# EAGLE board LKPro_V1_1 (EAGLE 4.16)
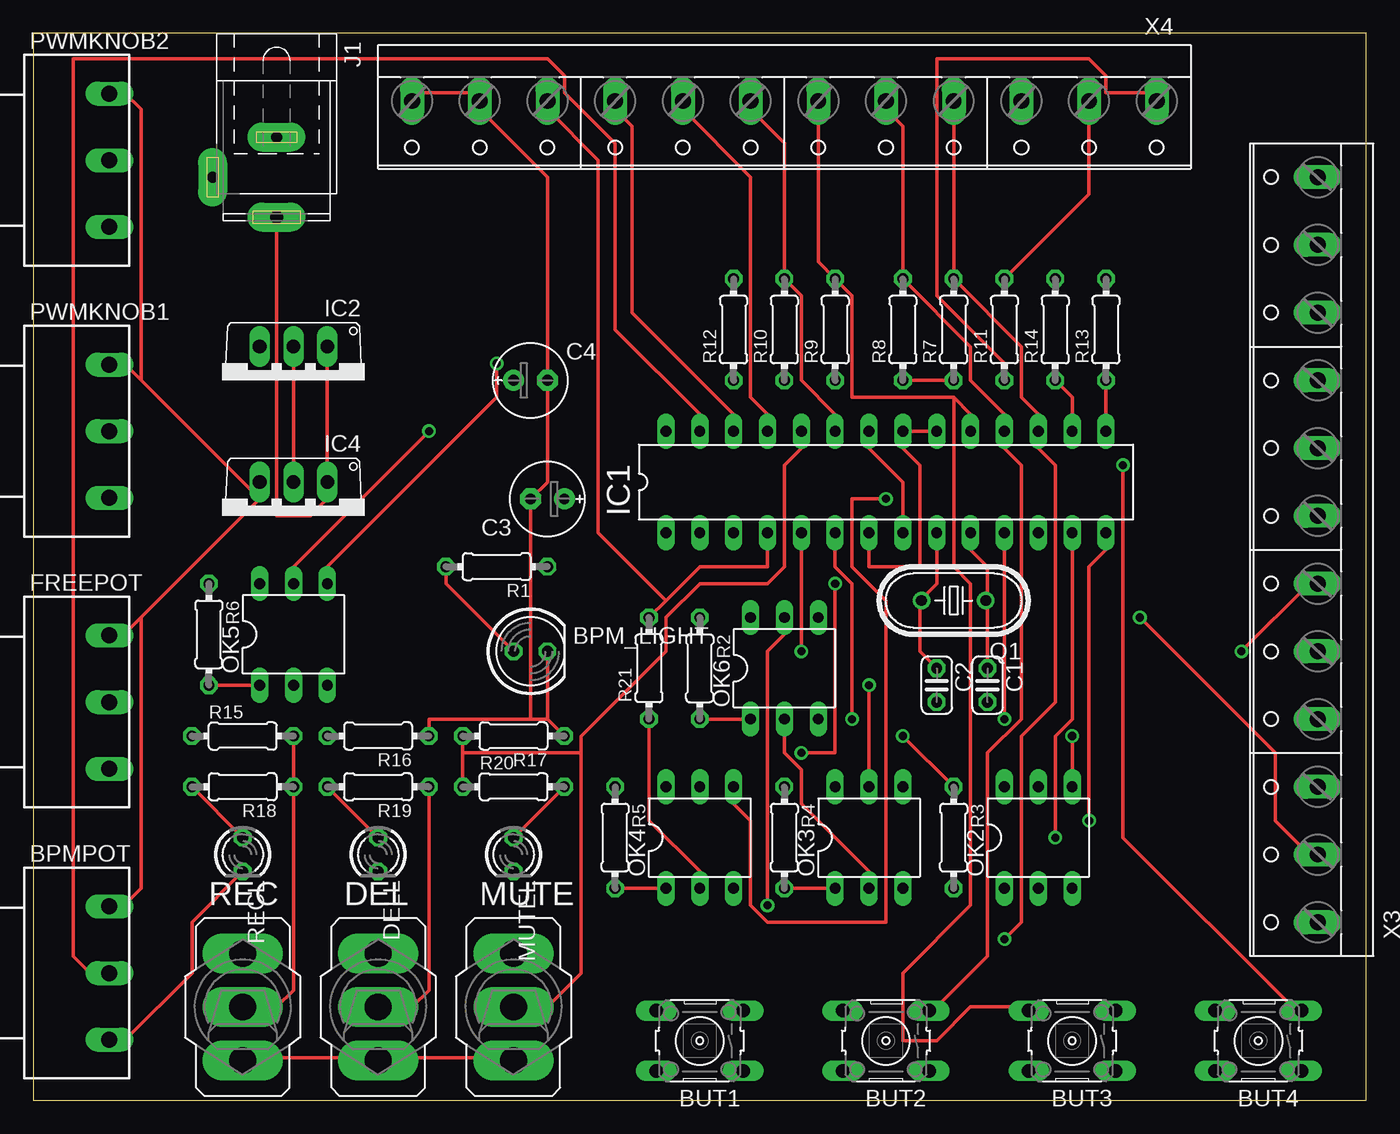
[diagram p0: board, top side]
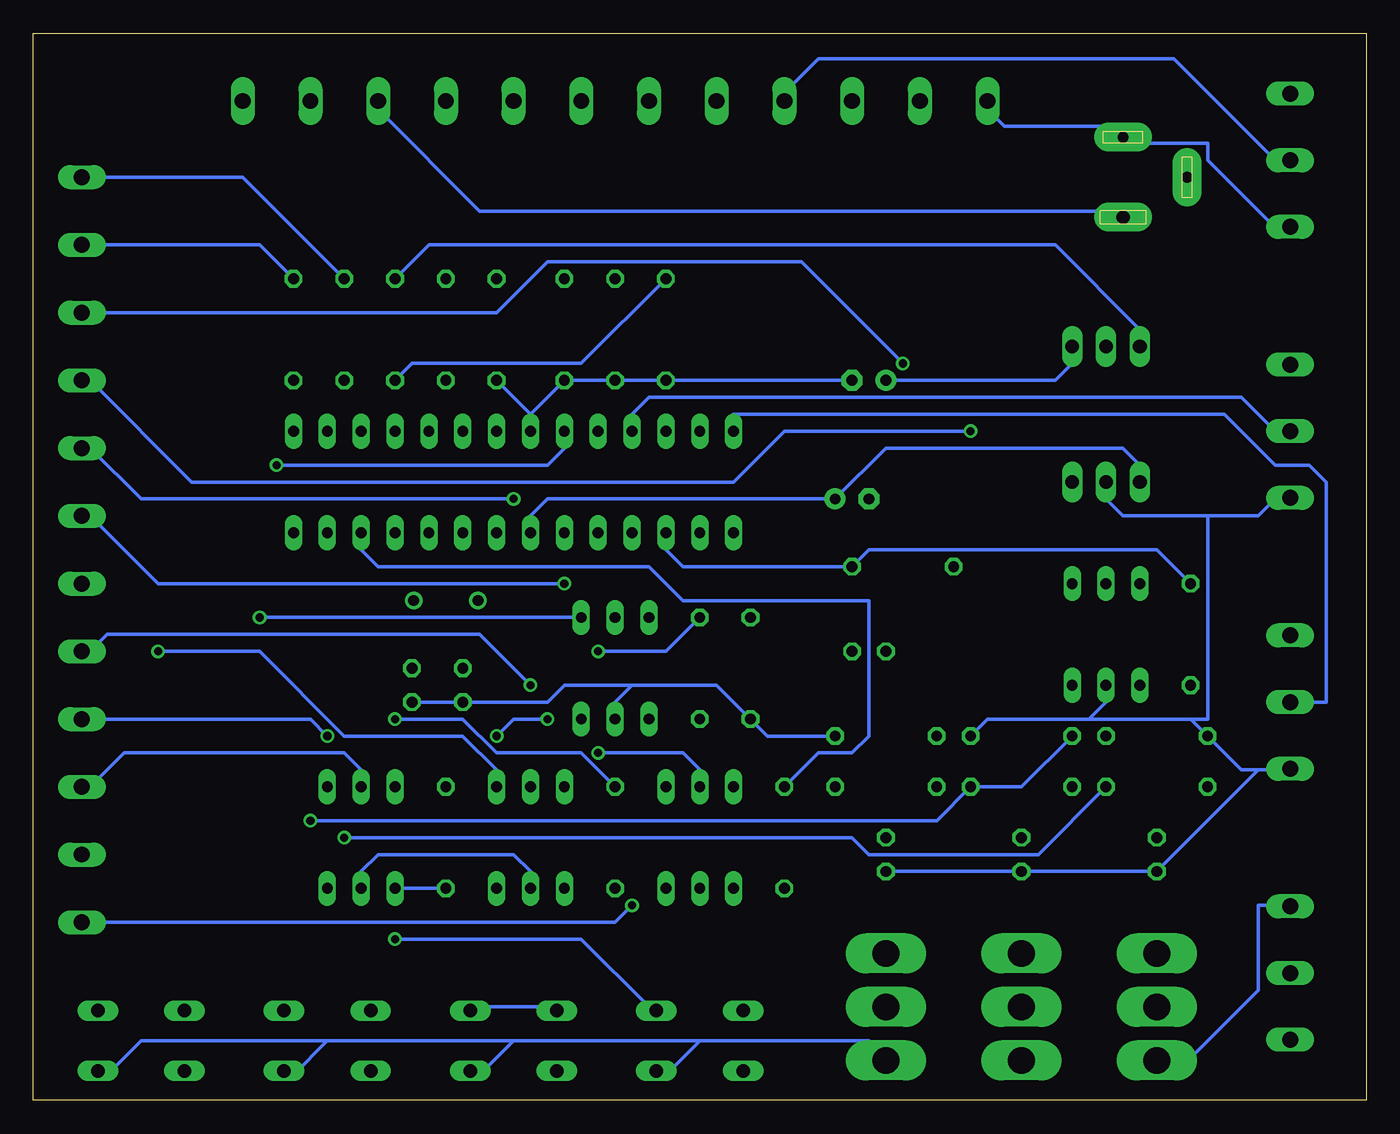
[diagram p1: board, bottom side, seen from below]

Size 100 x 80 mm. Coordinates in mm from the lower left corner, seen from the top.
Outline: 0,0 100,0 100,80 0,80 0,0
Copper layers (1*16): Top 0.035mm / dielectric 1.5mm / Bottom 0.035mm
Design rules "default": minimum track width 10mil, minimum drill 24mil, track to track 8mil, track to pad 8mil, pad to pad 8mil, via to via 8mil, smd to smd 8mil, copper to edge 40mil, drill to drill 8mil, minimum pad ring 10mil, minimum via ring 8mil, stop-mask expansion 4mil, vias tented up to drill 0mil, thermal gap 10mil

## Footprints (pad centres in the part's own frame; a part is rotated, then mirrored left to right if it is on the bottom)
LED5MM = drill 0.813 octagon: A -1.27,0; K 1.27,0
PC16S = drill 1.2 long: 1A -5,6.5; 1E 5,6.5; 1S 0,6.5
B3F-10XX = drill 1.016 long: 1 -3.251,2.261; 2 3.251,2.261; 3 -3.251,-2.261; 4 3.251,-2.261
C025-024X044 = drill 0.813 octagon: 1 -1.27,0; 2 1.27,0
E2,5-6E = drill 0.813 pad 1.575 round: + -1.27,0 | drill 0.813 pad 1.575 octagon: - 1.27,0
320-916 = drill 2.007 long: 1 0,4.013; 2 0,0; 3 0,-4.013
LED3MM = drill 0.813 octagon: A -1.27,0; K 1.27,0
DIL28-3 = drill 0.813 long: 1 -16.51,-3.81; 2 -13.97,-3.81; 3 -11.43,-3.81; 4 -8.89,-3.81; 5 -6.35,-3.81; 6 -3.81,-3.81; 7 -1.27,-3.81; 8 1.27,-3.81; 9 3.81,-3.81; 10 6.35,-3.81; 11 8.89,-3.81; 12 11.43,-3.81; 13 13.97,-3.81; 14 16.51,-3.81; 15 16.51,3.81; 16 13.97,3.81; 17 11.43,3.81; 18 8.89,3.81; 19 6.35,3.81; 20 3.81,3.81; 21 1.27,3.81; 22 -1.27,3.81; 23 -3.81,3.81; 24 -6.35,3.81; 25 -8.89,3.81; 26 -11.43,3.81; 27 -13.97,3.81; 28 -16.51,3.81
TO220V = drill 1.016 long: 1 -2.54,-2.54; 2 0,-2.54; 3 2.54,-2.54
SPC4077 = drill 0.8 pad 2.184 long: 1 -3,0; 2 0,-4.8 | drill 1 pad 2.184 long: 3 3,0
DIL06 = drill 0.813 long: 1 -2.54,-3.81; 2 0,-3.81; 3 2.54,-3.81; 4 2.54,3.81; 5 0,3.81; 6 -2.54,3.81
HC49U70 = drill 0.813 round: 1 -2.413,0; 2 2.413,0
0204/7 = drill 0.813 octagon: 1 -3.81,0; 2 3.81,0
W237-12P = drill 1.194 long: 1 -27.94,-0.635; 2 -22.86,-0.635; 3 -17.78,-0.635; 4 -12.7,-0.635; 5 -7.62,-0.635; 6 -2.54,-0.635; 7 2.54,-0.635; 8 7.62,-0.635; 9 12.7,-0.635; 10 17.78,-0.635; 11 22.86,-0.635; 12 27.94,-0.635

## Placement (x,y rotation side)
BPM_LIGHT  [LED5MM]  37.3,33.65 0 top
BPMPOT  PC16S  [PC16S]  -0.8,9.52 270 top
BUT1  [B3F-10XX]  50,4.44 180 top
BUT2  [B3F-10XX]  63.97,4.44 180 top
BUT3  [B3F-10XX]  77.94,4.44 180 top
BUT4  [B3F-10XX]  91.91,4.44 180 top
C1  22pF  [C025-024X044]  71.59,31.11 270 top
C2  22pF  [C025-024X044]  67.78,31.11 270 top
C3  1uF  [E2,5-6E]  38.57,45.08 180 top
C4  10uF  [E2,5-6E]  37.3,53.97 0 top
DEL  [320-916]  25.87,6.98 0 top
DELL  [LED3MM]  25.87,18.41 270 top
FREEPOT  PC16S  [PC16S]  -0.8,29.84 270 top
IC1  MEGA8-P  [DIL28-3]  63.97,46.35 0 top
IC2  7806  [TO220V]  19.52,53.97 180 top
IC4  7805  [TO220V]  19.52,43.81 180 top
J1  [SPC4077]  18.25,69.21 270 top
MUTE  [320-916]  36.03,6.98 0 top
MUTEL  [LED3MM]  36.03,18.41 270 top
OK2  4N35  [DIL06]  75.4,19.68 0 top
OK3  4N35  [DIL06]  62.7,19.68 0 top
OK4  4N35  [DIL06]  50,19.68 0 top
OK5  4N35  [DIL06]  19.52,34.92 0 top
OK6  4N35  [DIL06]  56.35,32.38 0 top
PWMKNOB1  PC16S  [PC16S]  -0.8,50.16 270 top
PWMKNOB2  PC16S  [PC16S]  -0.8,70.48 270 top
Q1  [HC49U70]  69.05,37.46 180 top
R1  220 Ohm  [0204/7]  34.76,40 180 top
R2  220 Ohm  [0204/7]  50,32.38 270 top
R3  220 Ohm  [0204/7]  69.05,19.68 270 top
R4  220 Ohm  [0204/7]  56.35,19.68 270 top
R5  220 Ohm  [0204/7]  43.65,19.68 270 top
R6  220 Ohm  [0204/7]  13.17,34.92 270 top
R7  1k Ohm  [0204/7]  69.05,57.78 90 top
R8  1k Ohm  [0204/7]  65.24,57.78 90 top
R9  1k Ohm  [0204/7]  60.16,57.78 90 top
R10  1k Ohm  [0204/7]  56.35,57.78 90 top
R11  1k Ohm  [0204/7]  72.86,57.78 90 top
R12  1k Ohm  [0204/7]  52.54,57.78 90 top
R13  220 Ohm  [0204/7]  80.48,57.78 90 top
R14  220 Ohm  [0204/7]  76.67,57.78 90 top
R15  1k Ohm  [0204/7]  15.71,27.3 0 top
R16  1k Ohm  [0204/7]  25.87,27.3 180 top
R17  1k Ohm  [0204/7]  36.03,27.3 180 top
R18  220 Ohm  [0204/7]  15.71,23.49 180 top
R19  220 Ohm  [0204/7]  25.87,23.49 180 top
R20  220 Ohm  [0204/7]  36.03,23.49 0 top
R21  1k Ohm  [0204/7]  46.19,32.38 90 top
REC  [320-916]  15.71,6.98 0 top
RECL  [LED3MM]  15.71,18.41 270 top
X3  [W237-12P]  95.72,41.27 90 top
X4  [W237-12P]  56.35,74.29 180 top

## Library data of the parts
BPM_LIGHT DELL MUTEL RECL = led
BPMPOT FREEPOT PWMKNOB1 PWMKNOB2 = piher
BUT1-BUT4 = switch-omron
C1-C4 R1-R21 = rcl
DEL MUTE REC = switch
IC1 = atmel
IC2 IC4 = linear
J1 = con-jack
OK2-OK6 = optocoupler
Q1 = crystal
X3 X4 = con-wago-508

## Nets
+12V: C4.+ IC2.1 IC4.1 J1.3 X4.3
GND: BPM_LIGHT.K BPMPOT.1E C1.2 C2.2 C3.- C4.- DELL.K FREEPOT.1E IC1.8 IC1.22 IC2.2 IC4.2 J1.1 MUTEL.K OK2.2 OK3.2 OK4.2 OK5.2 OK6.2 PWMKNOB1.1E PWMKNOB2.1E R7.1 R8.1 R9.1 R10.1 R12.1 R15.1 R16.1 R17.1 R21.1 RECL.K X4.11 X4.12
N$1: C2.1 IC1.9 Q1.2
N$2: C1.1 IC1.10 Q1.1
N$3: OK6.1 R2.2
N$4: BPMPOT.1A BUT1.1 BUT2.1 BUT3.1 BUT4.1 C3.+ DEL.3 FREEPOT.1A IC1.7 IC1.20 IC1.21 IC4.3 MUTE.3 PWMKNOB1.1A PWMKNOB2.1A REC.3
N$5: OK6.5 X3.1
N$6: IC1.3 R1.1 R6.1
N$7: BPM_LIGHT.A R1.2
N$8: OK2.1 R3.2
N$9: OK3.1 R4.2
N$10: OK4.1 R5.2
N$11: OK5.1 R6.2
N$12: OK6.4 X3.2
N$13: OK2.5 X3.3
N$14: OK2.4 X3.4
N$15: OK3.5 X3.5
N$16: OK3.4 X3.6
N$17: OK4.5 X3.7
N$18: OK4.4 X3.8
N$19: OK5.5 X3.9
N$20: OK5.4 X3.10
N$21: IC2.3 R11.2 X4.2
N$22: R11.1 R12.2 X4.1
N$23: DEL.2 IC1.14 R16.2 R19.1
N$24: IC1.5 R2.1
N$25: IC1.6 R3.1
N$26: IC1.11 R4.1
N$27: IC1.12 R5.1
N$28: BUT1.3 IC1.17 R7.2 X4.4
N$29: BUT2.3 BUT2.4 IC1.18 R8.2 X4.5
N$30: BUT3.4 IC1.19 R9.2 X4.6
N$31: BUT4.3 IC1.23 R10.2 X4.7
N$32: IC1.16 R14.1
N$33: IC1.15 R13.1
N$34: R13.2 X3.11
N$35: R14.2 X3.12
N$37: IC1.25 PWMKNOB1.1S X4.8
N$38: IC1.26 PWMKNOB2.1S X4.9
N$39: BPMPOT.1S IC1.27
N$40: R18.2 RECL.A
N$41: IC1.13 R15.2 R18.1 REC.2
N$42: IC1.24 MUTE.2 R17.2 R20.1
N$43: FREEPOT.1S IC1.28
N$44: MUTEL.A R20.2
N$45: DELL.A R19.2
N$47: IC1.4 R21.2 X4.10

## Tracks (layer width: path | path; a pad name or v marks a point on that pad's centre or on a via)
+12V
  Top 0.254: IC2.1 IC4.1 22.06,45.08 20.79,43.81 18.25,43.81 J1.3
  Bottom 0.254: C4.+ 23.33,53.97 22.06,55.24 IC2.1 | X4.3 74.13,74.29 66.51,66.67 19.52,66.67 J1.3
GND
  Top 0.254: X4.12 28.41,75.56 33.49,75.56 X4.11 33.49,74.29 38.57,69.21 C4.- 38.57,46.35 C3.- 37.3,28.57 | IC1.8 65.24,46.35 62.7,48.89 IC1.22 | R8.1 R7.1 | 38.57,28.57 R17.1 | 38.57,28.57 BPM_LIGHT.K | R21.1 46.19,20.95 50,17.14 OK4.2 | OK3.2 62.7,17.14 57.62,22.22 57.62,24.76 56.35,26.03 OK6.2 | RECL.K 11.9,13.33 11.9,9.52 6.82,4.44 BPMPOT.1E | IC4.2 IC2.2 | 37.3,28.57 29.68,28.57 R16.1 | 37.3,28.57 38.57,28.57
  Bottom 0.254: PWMKNOB2.1E 6.82,65.4 11.9,70.48 11.9,71.75 16.98,71.75 J1.1 19.52,73.02 27.14,73.02 28.41,74.29 X4.12 | 62.7,51.43 R9.1 R10.1 R12.1 C4.- | 62.7,51.43 R8.1 | 62.7,51.43 IC1.22 | C1.2 C2.2 61.43,29.84 60.16,31.11 55.08,31.11 | R17.1 44.92,27.3 R21.1 48.73,31.11 55.08,31.11 | 55.08,31.11 56.35,29.84 OK6.2 | OK2.2 75.4,17.14 74.13,18.41 63.97,18.41 62.7,17.14 OK3.2 | MUTEL.K DELL.K RECL.K 8.09,24.76 | 11.9,43.81 18.25,43.81 19.52,45.08 IC4.2 | 11.9,43.81 8.09,43.81 6.82,45.08 PWMKNOB1.1E | 8.09,24.76 6.82,24.76 FREEPOT.1E | 8.09,24.76 9.36,24.76 R15.1 13.17,28.57 | R16.1 28.41,28.57 20.79,28.57 | 20.79,28.57 19.52,29.84 OK5.2 | 13.17,28.57 20.79,28.57 | 11.9,43.81 11.9,28.57 13.17,28.57
N$1
  Top 0.254: 66.51,37.46 67.78,38.73 IC1.9 | C2.1 66.51,33.65 66.51,37.46 | 66.51,37.46 Q1.2
N$2
  Top 0.254: C1.1 71.59,37.46 | 71.59,37.46 71.59,40 70.32,41.27 IC1.10 | 71.59,37.46 Q1.1
N$3
  Top 0.254: R2.2 OK6.1
N$4
  Top 0.254: REC.3 18.25,3.17 23.33,3.17 DEL.3 28.41,3.17 33.49,3.17 MUTE.3 | IC1.20 IC1.21 65.24,48.89 66.51,47.62 66.51,40 62.7,40 IC1.7 | 8.09,36.19 6.82,34.92 FREEPOT.1A | 8.09,36.19 16.98,45.08 | 8.09,36.19 8.09,15.87 6.82,14.6 BPMPOT.1A | 16.98,45.08 8.09,53.97 | 8.09,53.97 6.82,55.24 PWMKNOB1.1A | 16.98,45.08 IC4.3 | 8.09,53.97 8.09,74.29 6.82,75.56 PWMKNOB2.1A
  Bottom 0.254: 50,4.44 52.54,1.9 BUT1.1 | 50,4.44 37.3,4.44 MUTE.3 | 63.97,4.44 66.51,1.9 BUT2.1 | 50,4.44 63.97,4.44 | 77.94,4.44 80.48,1.9 BUT3.1 | 63.97,4.44 77.94,4.44 | 77.94,4.44 91.91,4.44 94.45,1.9 BUT4.1 | IC1.7 62.7,43.81 61.43,45.08 C3.+ 36.03,48.89 18.25,48.89 16.98,47.62 IC4.3 | REC.3 13.17,3.17 8.09,8.25 8.09,14.6 6.82,14.6 BPMPOT.1A
N$5  (via drill 0.61)
  Top 0.254: v55.08,14.6 55.08,33.65 56.35,34.92 OK6.5
  Bottom 0.254: v55.08,14.6 56.35,13.33 X3.1
N$6
  Bottom 0.254: R6.1 15.71,41.27 37.3,41.27 R1.1 51.27,40 52.54,41.27 IC1.3
N$7
  Top 0.254: BPM_LIGHT.A 30.95,38.73 R1.2
N$8
  Bottom 0.254: R3.2 OK2.1
N$9
  Top 0.254: R4.2 OK3.1
N$10
  Top 0.254: R5.2 OK4.1
N$11
  Top 0.254: R6.2 OK5.1
N$12  (via drill 0.61)
  Top 0.254: v83.02,36.19 93.18,26.03 93.18,20.95 95.72,18.41 X3.2
  Bottom 0.254: OK6.4 v83.02,36.19
N$13
  Bottom 0.254: OK2.5 75.4,24.76 76.67,26.03 93.18,26.03 95.72,23.49 X3.3
N$14  (via drill 0.61)
  Top 0.254: OK2.4 v77.94,27.3
  Bottom 0.254: v77.94,27.3 79.21,28.57 X3.4
N$15  (via drill 0.61)
  Top 0.254: OK3.5 v62.7,31.11
  Bottom 0.254: v62.7,31.11 66.51,34.92 94.45,34.92 95.72,33.65 X3.5
N$16  (via drill 0.61)
  Top 0.254: v90.64,33.65 95.72,38.73 X3.6
  Bottom 0.254: v90.64,33.65 83.02,33.65 76.67,27.3 67.78,27.3 65.24,24.76 OK3.4
N$17  (via drill 0.61)
  Top 0.254: v57.62,26.03 60.16,26.03 v60.16,38.73
  Bottom 0.254: v57.62,26.03 51.27,26.03 50,24.76 OK4.5 | v60.16,38.73 90.64,38.73 95.72,43.81 X3.7
N$18  (via drill 0.61)
  Top 0.254: v63.97,45.08 61.43,45.08 61.43,40 63.97,37.46 63.97,13.33 55.08,13.33 53.81,14.6 53.81,20.95 52.54,22.22 OK4.4
  Bottom 0.254: v63.97,45.08 91.91,45.08 95.72,48.89 X3.8
N$19  (via drill 0.61)
  Top 0.254: v29.68,50.16 19.52,40 OK5.5
  Bottom 0.254: v29.68,50.16 43.65,50.16 47.46,46.35 88.1,46.35 95.72,53.97 X3.9
N$20  (via drill 0.61)
  Top 0.254: v34.76,55.24 34.76,52.7 22.06,40 OK5.4
  Bottom 0.254: v34.76,55.24 42.38,62.86 61.43,62.86 65.24,59.05 X3.10
N$21
  Top 0.254: R11.2 79.21,67.94 X4.2
  Bottom 0.254: R11.2 70.32,64.13 23.33,64.13 16.98,57.78 IC2.3
N$22
  Top 0.254: R11.1 72.86,55.24 67.78,60.32 67.78,78.1 79.21,78.1 80.48,76.83 80.48,75.56 84.29,75.56 X4.1
  Bottom 0.254: R12.2 58.89,55.24 71.59,55.24 R11.1
N$23  (via drill 0.61)
  Top 0.254: v79.21,20.95 79.21,40 80.48,41.27 IC1.14 | R19.1 29.68,8.25 28.41,6.98 DEL.2
  Bottom 0.254: R16.2 25.87,23.49 R19.1 32.22,20.95 v79.21,20.95
N$24  (via drill 0.61)
  Top 0.254: v57.62,33.65 IC1.5
  Bottom 0.254: R2.1 52.54,33.65 v57.62,33.65
N$25  (via drill 0.61)
  Top 0.254: v65.24,27.3 R3.1 | v61.43,28.57 61.43,38.73 60.16,40 IC1.6
  Bottom 0.254: v65.24,27.3 63.97,28.57 v61.43,28.57
N$26  (via drill 0.61)
  Top 0.254: v72.86,28.57 IC1.11
  Bottom 0.254: R4.1 58.89,26.03 65.24,26.03 67.78,28.57 v72.86,28.57
N$27
  Bottom 0.254: R5.1 41.11,26.03 38.57,26.03 37.3,27.3 37.3,37.46 51.27,37.46 53.81,40 74.13,40 75.4,41.27 IC1.12
N$28  (via drill 0.61)
  Top 0.254: v72.86,12.06 74.13,13.33 74.13,27.3 76.67,29.84 76.67,47.62 75.4,48.89 IC1.17 75.4,51.43 74.13,52.7 74.13,56.51 R7.2 X4.4
  Bottom 0.254: v72.86,12.06 58.89,12.06 53.81,6.98 BUT1.3
N$29
  Top 0.254: X4.5 63.97,74.29 65.24,73.02 R8.2 70.32,56.51 70.32,53.97 72.86,51.43 IC1.18 72.86,48.89 74.13,47.62 74.13,28.57 71.59,26.03 71.59,10.79 67.78,6.98 BUT2.3
  Bottom 0.254: BUT2.4 61.43,6.98 66.51,6.98 BUT2.3
N$30
  Top 0.254: X4.6 58.89,62.86 R9.2 61.43,60.32 61.43,52.7 69.05,52.7 | 69.05,52.7 70.32,51.43 IC1.19 | 69.05,52.7 69.05,40 70.32,38.73 70.32,14.6 65.24,9.52 65.24,4.44 67.78,4.44 70.32,6.98 74.13,6.98 BUT3.4
N$31  (via drill 0.61)
  Top 0.254: IC1.23 60.16,51.43 57.62,53.97 57.62,60.32 R10.2 56.35,71.75 53.81,74.29 X4.7 | v81.75,47.62 81.75,19.68 94.45,6.98 BUT4.3
  Bottom 0.254: v81.75,47.62 61.43,47.62 60.16,48.89 IC1.23
N$32
  Top 0.254: R14.1 77.94,52.7 IC1.16
N$33
  Top 0.254: IC1.15 R13.1
N$34
  Bottom 0.254: R13.2 83.02,64.13 X3.11
N$35
  Bottom 0.254: R14.2 84.29,69.21 X3.12
N$37
  Top 0.254: IC1.25 55.08,51.43 53.81,52.7 53.81,69.21 48.73,74.29 X4.8
  Bottom 0.254: PWMKNOB1.1S 6.82,50.16 9.36,52.7 53.81,52.7 55.08,51.43 IC1.25
N$38
  Top 0.254: IC1.26 52.54,51.43 44.92,59.05 44.92,73.02 43.65,74.29 X4.9
  Bottom 0.254: PWMKNOB2.1S 6.82,70.48 14.44,78.1 41.11,78.1 43.65,75.56 X4.9
N$39
  Top 0.254: IC1.27 50,51.43 43.65,57.78 43.65,71.75 39.84,75.56 39.84,76.83 38.57,78.1 3.01,78.1 3.01,10.79 4.28,9.52 BPMPOT.1S
N$40
  Top 0.254: R18.2 RECL.A
N$41  (via drill 0.61)
  Top 0.254: R15.2 R18.1 19.52,8.25 18.25,6.98 REC.2 | v76.67,19.68 76.67,27.3 77.94,28.57 IC1.13
  Bottom 0.254: v76.67,19.68 38.57,19.68 37.3,18.41 24.6,18.41 R18.1
N$42
  Top 0.254: 32.22,26.03 R17.2 | 32.22,26.03 R20.1 | 41.11,26.03 41.11,9.52 38.57,6.98 MUTE.2 | 41.11,26.03 41.11,27.3 47.46,33.65 47.46,36.19 50,38.73 55.08,38.73 56.35,40 56.35,47.62 57.62,48.89 IC1.24 | 41.11,26.03 32.22,26.03
N$43
  Bottom 0.254: IC1.28 47.46,51.43 10.63,51.43 6.82,47.62 4.28,47.62 3.01,46.35 3.01,29.84 FREEPOT.1S
N$44
  Top 0.254: MUTEL.A R20.2
N$45
  Top 0.254: DELL.A R19.2
N$47
  Top 0.254: 47.46,37.46 50,40 55.08,40 IC1.4 | R21.2 47.46,37.46 | 47.46,37.46 42.38,42.54 42.38,70.48 38.57,74.29 X4.10

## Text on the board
tDocu: pwm2 | gnd | gnd | +6v | +3v | clckin | butt4 | butt3 | butt2 | butt1 | 6-12v | pwm1 | pwmknob2 | pwmknob1 | clck | clck | ch4 | ch4 | ch3 | ch3 | ch2 | ch2 | ch1 | REC | DEL | MUTE | MUTE | ch1 | ch1 | ch2 | ch3 | ch4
